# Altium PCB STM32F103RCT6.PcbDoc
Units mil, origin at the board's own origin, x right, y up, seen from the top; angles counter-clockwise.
Board outline 6000 x 4000 mil, 2 copper layers (Top Layer, Bottom Layer); 77 components, 70 nets, 370 pads, 115 vias.
Unrouted connection lines stored in the file: 1.
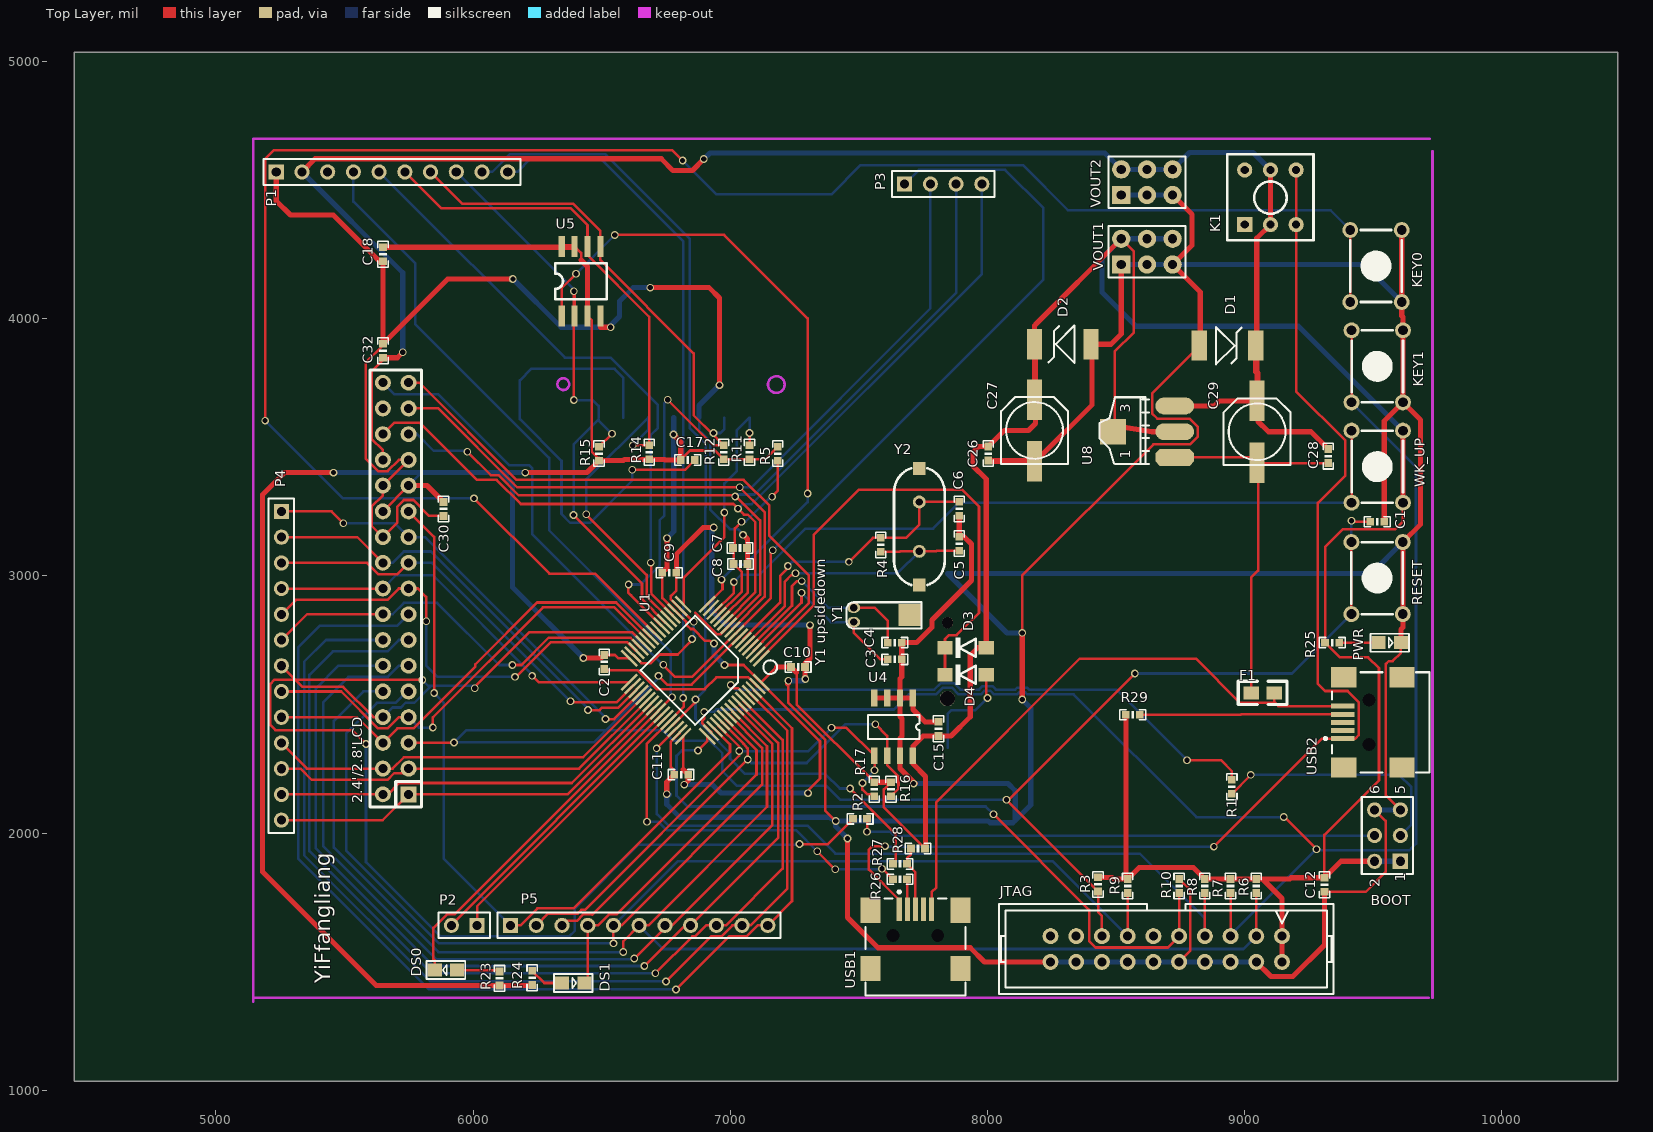
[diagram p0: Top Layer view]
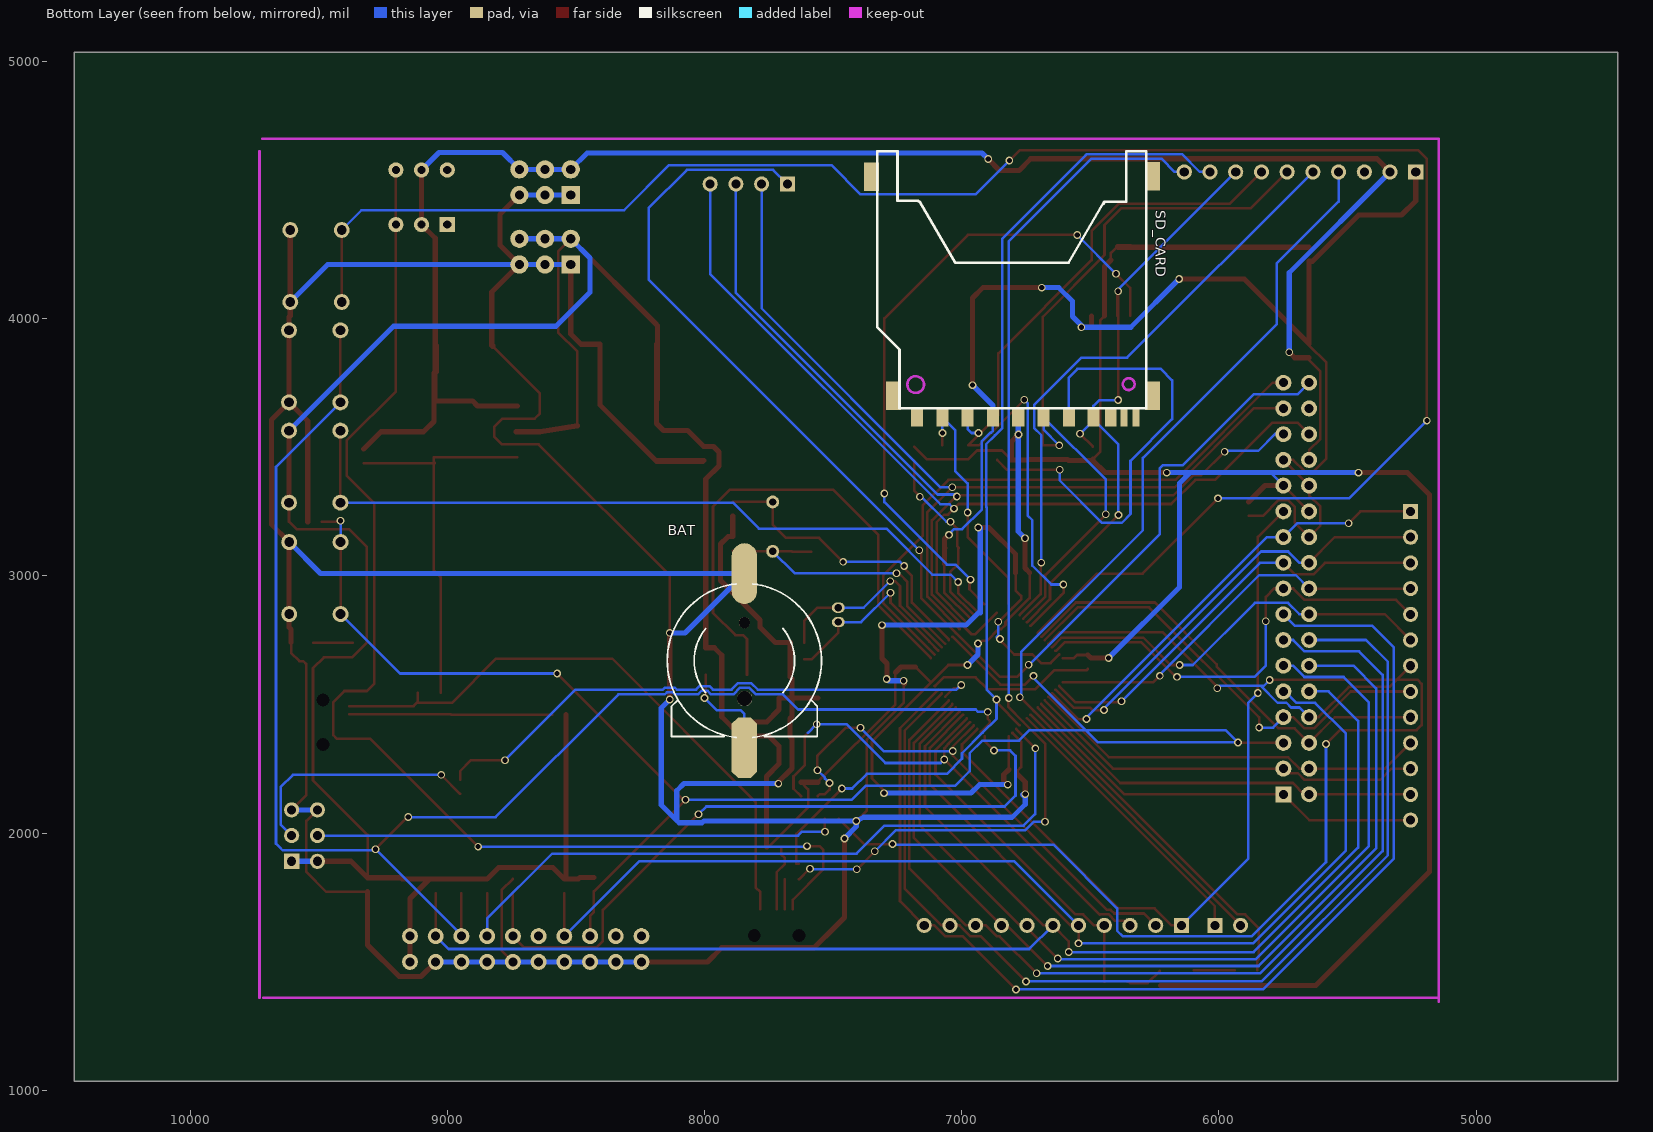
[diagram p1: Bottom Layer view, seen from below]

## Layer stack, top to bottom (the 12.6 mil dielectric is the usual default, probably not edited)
Top Layer: signal copper 1.4
Dielectric: dielectric 12.6, FR-4, Dk 4.8
Bottom Layer: signal copper 1.4

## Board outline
4450,1035 10450,1035 10450,5035 4450,5035

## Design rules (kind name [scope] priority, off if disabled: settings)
Clearance [All] p1: gap=8
PolygonConnect [All] p1: connectstyle=Relief reliefconductorwidth=10 reliefentries=4 polygonreliefangle="90 Angle" airgapwidth=10
RoutingVias [All] p1: holewidth=2 width=50 viastyle="Through Hole" minholewidth=1 minwidth=1 maxholewidth=200 maxwidth=300
SMDNeckDown [All] p1: percent=80.000
SolderMaskExpansion [All] p1: expansion=4
UnConnectedPin [All] p1:
Width Width_3 [InNet('GND')] p1: maxlimit=20 minlimit=10 preferedwidth=20
Width Width_2 [InNet('VCC3.3')] p2: maxlimit=20 minlimit=10 preferedwidth=20
Width Width_1 [InNet('VCC5')] p3: maxlimit=20 minlimit=10 preferedwidth=20
Width [All] p4: maxlimit=10 minlimit=10 preferedwidth=10
28 further rules are at their usual default settings.

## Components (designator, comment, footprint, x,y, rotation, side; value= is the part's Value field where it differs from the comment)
2.4'/2.8'LCD "TFT_LCD" HEAD2*17 5750,2150 r90 top
BAT "BATT" BATM 7845,2670 r180 bottom
BOOT "Header 3X2" HDR2X3#1 9605,1890 r90 top
C1 "104" 0603P 9515,3210 r0 top
C2 "104" 0603P 6510,2665 r270 top
C3 "22" 0603P 7640,2675 r180 top
C4 "22" 0603P 7640,2740 r180 top
C5 "22" 0603P 7890,3125 r270 top
C6 "22" 0603P 7890,3260 r90 top
C7 "10uF" 0603P 7038,3108 r0 top
C8 "104" 0603P 7040,3046 r0 top
C9 "104" 0603P 6763,3012 r0 top
C10 "104" 0603P 7264,2645 r180 top
C11 "104" 0603P 6809,2227 r0 top
C12 "104" 0603P 9310,1799 r270 top
C15 "104" 0603P 7810,2405 r270 top
C17 "104" 0603P 6835,3450 r180 top
C18 "104" 0603P 5650,4250 r270 top
C26 "104" 0603P 8003,3475 r90 top
C27 "220uF" CC6.56.5 8183,3565 r270 top
C28 "104" 0603P 9325,3465 r90 top
C29 "220uF" CC6.56.5 9048,3560 r270 top
C30 "104" 0603P 5885,3260 r270 top
C32 "104" 0603P 5650,3875 r270 top
D1 "SMBJ5.0A" SMBJ 8928,3895 r0 top
D2 "SMBJ3.3A" SMBJ 8298,3900 r180 top
D3 "1N4148" DIODE_SOP 7915,2720 r180 top
D4 "" DIODE_SOP 7915,2615 r180 top
DS0 "LED1" SMDLED 5938,1467 r180 top
DS1 "LED2" SMDLED 6346,1417 r0 top
F1 "500mA" 0805 9025,2545 r0 top
JTAG "JTAG" JTAG_20 8695,1549 r180 top
K1 "BUTTON" BTN8.5*8.5 9000,4365 r90 top
KEY0 "KEY_M" KEY_M 9610,4345 r270 top
KEY1 "KEY_M" KEY_M 9615,3955 r270 top
P1 "VS1053b" HDR1X10 5235,4570 r0 top
P2 "USART" HDR1X2 6016,1641 r180 top
P3 "Header 4" HDR1X4 7678,4523 r0 top
P4 "Header 13" HDR1X13 5255,3250 r270 top
P5 "Header 11" HDR1X11 6146,1641 r0 top
PWR "SYS" SMDLED 9520,2740 r0 top
R1 "Res2" 0603P 8950,2180 r270 top
R2 "Res2" 0603P 7505,2055 r180 top
R3 "Res2" 0603P 8430,1800 r90 top
R4 "1M" 0603P 7585,3120 r90 top
R5 "10R" 0603P 7185,3475 r270 top
R6 "" 0603P 9045,1794 r270 top
R7 "" 0603P 8945,1794 r270 top
R8 "" 0603P 8845,1794 r270 top
R9 "" 0603P 8545,1794 r270 top
R10 "" 0603P 8745,1794 r90 top
R11 "45K" 0603P 7075,3480 r270 top
R12 "45K" 0603P 6975,3480 r270 top
R14 "45K" 0603P 6685,3480 r270 top
R15 "45K" 0603P 6490,3475 r270 top
R16 "" 0603P 7625,2170 r90 top
R17 "" 0603P 7560,2170 r90 top
R23 "1.5K" 0603P 6103,1435 r270 top
R24 "1.5K" 0603P 6230,1437 r270 top
R25 "1.5K" 0603P 9340,2740 r180 top
R26 "22R" 0603P 7660,1820 r0 top
R27 "22R" 0603P 7660,1880 r0 top
R28 "1.5K" 0603P 7730,1940 r180 top
R29 "1.5K" 0603P 8565,2460 r0 top
RESET "KEY_M" KEY_M 9415,2850 r90 top
SD_CARD "sd card" SDCARD_L 7075,3615 r0 bottom
U1 "STM32F103RCT6" LQFP64 7120,2680 r225 top
U4 "24C02" SOP-8 7710,2525 r270 top
U5 "W25Q64" SOIC-8 6345,4010 r90 top
U8 "AMS1117-3.3" AMS1117 8728,3460 r90 top
USB1 "USB" USB/SM0.8-6H5 7720,1395 r270 top
USB2 "USB" USB/SM0.8-6H5 9690,2430 r0 top
VOUT1 "VCC3.3" HDR2X3#2 8520,4210 r0 top
VOUT2 "VCC5" HDR2X3#2 8520,4480 r0 top
WK_UP "KEY_M" KEY_M 9615,3565 r270 top
Y1 "32.768K" XTAL32 7480,2820 r0 top
Y2 "8MHz" XTAL_US 7735,3095 r90 top

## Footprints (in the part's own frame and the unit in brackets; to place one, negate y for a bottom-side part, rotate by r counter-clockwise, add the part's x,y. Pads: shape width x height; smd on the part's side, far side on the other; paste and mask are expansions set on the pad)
0603P [mil]
  rect 30x30 smd: 1(-27,0) 2(27.5,-0.06)
  silkscreen extent -50,-20 50,20
0805 [mil]
  rect 60x50 smd: 1(0,-0.06) 2(90,-0.06)
  silkscreen extent -50,-45 140,45
AMS1117 [mil]
  oct 65x150 smd: 1(0.03,-0.06)
  oval 65x150 smd: 2(100.03,-0.06) 3(200.03,-0.06)
  rect 100x100 smd: 4(100.03,239.94)
  silkscreen extent -26,100 234,293
BATM [mm] "BAT"
  round 1.1 hole 1.1 unplated: 0(0,3.748)
  round 1.5 hole 1.5 unplated: 0(0.025,-3.752)
  oct 2.5x6 smd: 1(0,-8.602)
  oval 2.5x6 smd: 2(0,8.598)
  silkscreen extent -7.62,-7.58 7.62,7.57
BTN8.5*8.5 [mm]
  rect 1.5x1.5 hole 0.8: 1(0,0)
  round 1.5 hole 0.8: 2(0,-2.54) 3(0,-5.08) 4(5.4,-5.08) 5(5.4,-2.54) 6(5.4,0)
  silkscreen extent -1.55,-6.79 6.95,1.71
CC6.56.5 [mm] "SMD;W:6.5mm;L:6.5mm;"
  rect 4x1.5 smd: 1(-3.048,0) 2(3.048,0)
  silkscreen extent -3.3,-3.3 3.3,3.3
DIODE_SOP [mm] "4148"
  rect 1.5x1.3 smd: 1(-2.032,0) 2(2.032,0)
  silkscreen extent -1.02,-1.02 1.02,1.02
HDR1X2 [mm] "Connector; Header; 2 Position"
  rect 1.5x1.5 hole 0.9: 1(0,0)
  round 1.5 hole 0.9: 2(2.54,0)
  silkscreen extent -1.27,-1.27 3.81,1.27
HDR1X4 [mm] "Connector; Header; 4 Position"
  rect 1.5x1.5 hole 0.9: 1(0,0)
  round 1.5 hole 0.9: 2(2.54,0) 3(5.08,0) 4(7.62,0)
  silkscreen extent -1.27,-1.27 8.89,1.27
HDR1X10 [mm] "Connector; Header; 10 Position"
  rect 1.5x1.5 hole 0.9: 1(0,0)
  round 1.5 hole 0.9: 2(2.54,0) 3(5.08,0) 4(7.62,0) 5(10.16,0) 6(12.7,0) 7(15.24,0) 8(17.78,0) 9(20.32,0) 10(22.86,0)
  silkscreen extent -1.27,-1.27 24.13,1.27
HDR1X11 [mm] "Connector; Header; 11 Position"
  rect 1.5x1.5 hole 0.9: 1(0,0)
  round 1.5 hole 0.9: 2(2.54,0) 3(5.08,0) 4(7.62,0) 5(10.16,0) 6(12.7,0) 7(15.24,0) 8(17.78,0) 9(20.32,0) 10(22.86,0) 11(25.4,0)
  silkscreen extent -1.27,-1.27 26.67,1.27
HDR1X13 [mm] "Connector; Header; 13 Position"
  rect 1.5x1.5 hole 0.9: 1(0,0)
  round 1.5 hole 0.9: 2(2.54,0) 3(5.08,0) 4(7.62,0) 5(10.16,0) 6(12.7,0) 7(15.24,0) 8(17.78,0) 9(20.32,0) 10(22.86,0) 11(25.4,0) 12(27.94,0) 13(30.48,0)
  silkscreen extent -1.27,-1.27 31.75,1.27
HDR2X3#1 [mm] "Connector; Header; 3x2 Position"
  rect 1.5x1.5 hole 0.9: 1(0,0)
  round 1.5 hole 0.9: 2(0,2.54) 3(2.54,0) 4(2.54,2.54) 5(5.08,0) 6(5.08,2.54)
  silkscreen extent -1.27,-1.27 6.35,3.81
HDR2X3#2 [mm] "Connector; Header; 3x2 Position"
  rect 1.8x1.8 hole 0.9: 1(0,0)
  round 1.8 hole 0.9: 2(0,2.54) 3(2.54,0) 4(2.54,2.54) 5(5.08,0) 6(5.08,2.54)
  silkscreen extent -1.27,-1.27 6.35,3.81
HEAD2*17 [mil] "PIN:2.54mm;HEAD;"
  rect 62x62 hole 35: 1(0.43,0.42)
  round 62 hole 35: 2(0.43,100.42) 3(100.43,0.42) 4(100.43,100.42) 5(200.43,0.42) 6(200.43,100.42) 7(300.43,0.42) 8(300.43,100.42) 9(400.43,0.42) 10(400.43,100.42) 11(500.43,0.42) 12(500.43,100.42) 13(600.43,0.42) 14(600.43,100.42) 15(700.43,0.42) 16(700.43,100.42) 17(800.43,0.42) 18(800.43,100.42) 19(900.43,0.42) 20(900.43,100.42) 21(1000.43,0.42) 22(1000.43,100.42) 23(1100.43,0.42) 24(1100.43,100.42) 25(1200.43,0.42) 26(1200.43,100.42) 27(1300.43,0.42) 28(1300.43,100.42) 29(1400.43,0.42) 30(1400.43,100.42) 31(1500.43,0.42) 32(1500.43,100.42) 33(1600.43,0.42) 34(1600.43,100.42)
  silkscreen extent -50,-50 1650,150
JTAG_20 [mil] "JTAG,20PIN"
  round 62 hole 35: 1(-450,-50) 2(-450,50) 3(-350,-50) 4(-350,50) 5(-250,-50) 6(-250,50) 7(-150,-50) 8(-150,50) 9(-50,-50) 10(-50,50) 11(50,-50) 12(50,50) 13(150,-50) 14(150,50) 15(250,-50) 16(250,50) 17(350,-50) 18(350,50) 19(450,-50) 20(450,50)
  silkscreen extent -650,-175 650,175
KEY_M [mil] "KEY_MID"
  round 62 hole 38: 1(0.88,0.29) 1(280.85,0.29) 2(0.88,-199.71) 2(280.85,-199.71)
  silkscreen extent 1,-200 281,0
LQFP64 [mm] "LQFP64"
  rect 2.2x0.254 smd: 1(0,0) 2(0,-0.5) 3(0,-1) 4(0,-1.5) 5(0,-2) 6(0,-2.5) 7(0,-3) 8(0,-3.5) 9(0,-4) 10(0,-4.5) 11(0,-5) 12(0,-5.5) 13(0,-6) 14(0,-6.5) 15(0,-7) 16(0,-7.5) 33(10.9,-7.5) 34(10.9,-7) 35(10.9,-6.5) 36(10.9,-6) 37(10.9,-5.5) 38(10.9,-5) 39(10.9,-4.5) 40(10.9,-4) 41(10.9,-3.5) 42(10.9,-3) 43(10.9,-2.5) 44(10.9,-2) 45(10.9,-1.5) 46(10.9,-1) 47(10.9,-0.5) 48(10.9,0)
  rect 0.254x2.2 smd: 17(1.7,-9.2) 18(2.2,-9.2) 19(2.7,-9.2) 20(3.2,-9.2) 21(3.7,-9.2) 22(4.2,-9.2) 23(4.7,-9.2) 24(5.2,-9.2) 25(5.7,-9.2) 26(6.2,-9.2) 27(6.7,-9.2) 28(7.2,-9.2) 29(7.7,-9.2) 30(8.2,-9.2) 31(8.7,-9.2) 32(9.2,-9.2) 49(9.2,1.7) 50(8.7,1.7) 51(8.2,1.7) 52(7.7,1.7) 53(7.2,1.7) 54(6.7,1.7) 55(6.2,1.7) 56(5.7,1.7) 57(5.2,1.7) 58(4.7,1.7) 59(4.2,1.7) 60(3.7,1.7) 61(3.2,1.7) 62(2.7,1.7) 63(2.2,1.7) 64(1.7,1.7)
  silkscreen extent -0.68,-7.56 9.26,1.95
SDCARD_L [mm] "SDCARD_LARGE"
  rect 1.2x1.8 smd: 1(0,0) 2(-2.489,0) 3(-4.983,-0.009) 4(-7.483,-0.009) 5(-9.983,-0.009) 6(-12.483,-0.009) 7(-14.908,-0.009) 9(2.517,-0.009)
  rect 1.1x1.8 smd: 8(-16.612,0)
  rect 0.7x1.8 smd: 10(-17.908,-0.009) 12(-19.101,0)
  rect 1.5x2.8 smd: 11(-20.726,-23.834) 11(-20.726,-2.143) 11(4.826,-2.143) 11(7.01,-23.784)
  Keep-Out Layer circle w0.254: c2.642,-3.26 r0.82
  Keep-Out Layer circle w0.254: c-18.39,-3.3 r0.58
  silkscreen extent -20.13,-26.3 6.44,-0.9
SMBJ [mm]
  rect 1.5x3 smd: 1(-2.667,0) 2(2.921,0)
  silkscreen extent -1.02,-1.85 1.52,1.83
SMDLED [mm]
  rect 1.4x1.27 smd: 1(0.001,-0.002) 2(2.211,-0.002)
  silkscreen extent -0.8,-0.89 3.01,0.89
SOIC-8 [mil] "SOIC"
  rect 80x24 smd: 1(0,0) 2(0,-50.06) 3(0,-100.06) 4(0,-150.06) 5(270,-150) 6(270,-100) 7(270,-50) 8(270,0)
  silkscreen extent 65,-175 205,25
SOP-8 [mil] "SOP"
  rect 65x25 smd: 1(0,0) 2(0,-50) 3(0,-100) 4(0,-150) 5(224.41,-150) 6(224.41,-100) 7(224.41,-50) 8(224.41,0)
  silkscreen extent 65,-175 159,25
USB/SM0.8-6H5 [mm]
  rect 2.3x0.5 smd: 1(-7.85,-1.6) 2(-7.85,-0.8) 3(-7.85,0) 4(-7.85,0.8) 5(-7.85,1.6)
  rect 2.5x2 smd: 6(-7.75,4.45) 7(-1.996,4.45) 8(-7.75,-4.45) 9(-1.996,-4.45)
  round 0.6 hole 1.27 unplated: MH1(-5.25,2.2) MH2(-5.25,-2.2)
  silkscreen extent -9.67,-4.95 0.7,4.95
XTAL32 [mil]
  oval 50x40 hole 28: 1(0,0) 2(0,56)
  rect 92.13x86 smd: ""(220,27)
  silkscreen extent -28,-25 264,77
XTAL_US [mil]
  round 50 hole 28: 1(0,0) 2(192.13,0)
  rect 50x50 smd: ""(-130.32,0) ""(322.44,0)
  silkscreen extent -131,-98 323,98

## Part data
BAT: library part BAT
BOOT: "Header, 3-Pin, Dual row"
C1 C2 C3 C4 C5 C6 C7 C8 C9 C10 C11 C12 C15 C17 C18 C26 C28 C30 C32: library part C
C27 C29: library part CAP
D1 D2: library part SMBJ, "TVS"
D3: library part D
D4: library part D, "1N4148"
DS0 PWR: library part LED2, "Typical RED, GREEN, YELLOW, AMBER GaAs LED"
DS1: "Typical RED, GREEN, YELLOW, AMBER GaAs LED"
F1 R4 R5 R11 R12 R14 R15 R23 R24 R25 R26 R27 R28 R29: library part R
P1: library part "Header 10", "Header, 10-Pin"
P2: library part "Header 2", "Header, 2-Pin"
P3: "Header, 4-Pin"
P4: "Header, 13-Pin"
P5: "Header, 11-Pin"
R1 R2 R3: "Resistor"
R6 R7 R8 R9 R10 R16 R17: library part Res2, "Resistor"
U1: library part STM32F103RDT6
U4: library part 24C256
U5: library part W25X16, "W25X16;SST25VF016;MX25L1605"
U8: library part AMS1117
USB1 USB2: library part USB5
VOUT1 VOUT2: library part "Header 3X2", "Header, 3-Pin, Dual row"
Y1 Y2: library part XTAL, "Crystal Oscillator"

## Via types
v1: diameter 30, hole 20, Top Layer to Bottom Layer, 115 vias

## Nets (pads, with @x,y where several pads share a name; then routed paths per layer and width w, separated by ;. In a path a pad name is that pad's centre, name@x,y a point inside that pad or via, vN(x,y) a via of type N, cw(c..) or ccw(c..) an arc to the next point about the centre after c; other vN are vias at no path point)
BOOT0: R1.1 U1.60 | length 2241.9
  Top Layer w10: v1(7002,2575) 7014.09,2562.91 7031.08,2562.91 U1.60 ; v1(8776,2283) 8907,2283 8950,2240 R1.1
  Bottom Layer w10: v1(7002,2575) 7002,2576 7021,2557 7793.12,2557 7818.94,2582.83 7869.09,2582.83 7894.91,2557 7966.95,2557 7980.95,2571 8019.05,2571 8033.05,2557 8107.95,2557 8115.95,2565 8154.05,2565 8162.05,2557 8502,2557 v1(8776,2283)
BOOT1: 2.4'/2.8'LCD.8 P4.7 R2.2 U1.28 | length 5563.4
  Top Layer w10: P4.7 5337,2568 5495.23,2568 5612.81,2450.43 2.4'/2.8'LCD.8 ; v1(5584,2346) 5530,2400 5232,2400 5212,2420 5212,2580 5227,2595 v1(5803,2595) ; v1@6003.5,2565.5 6218,2780 6619.12,2780 U1.28 ; v1(7269,1957) 7379.44,1957 R2.2
  Bottom Layer w10: v1(5584,2346) 5584,1887 5873,1598 6374,1598 6396,1620 6396,1707 6644,1955 v1@7261,1955 ; 2.4'/2.8'LCD.8 5687.15,2488 5720,2488 5738.43,2506.43 5771.83,2506.43 5837.4,2572 ; v1(5803,2595) 5826,2572 5837.4,2572 ; v1(6007,2563) 5998,2572 5837.4,2572
F_CS: U1.16 U5.1 | length 2580.3
  Top Layer w10: U5.1 6345,4119 v1(6400,4174) ; v1(6551,4325) 6976,4325 7301,4000 v1(7301,3320) ; U1.16 6970,2947.58 6970,2981 v1(6966,2985)
  Bottom Layer w10: v1(6400,4174) v1(6551,4325) ; v1(6966,2985) 7024.45,3043.45 7057.55,3043.45 7301,3286.89 v1(7301,3320)
GND: 2.4'/2.8'LCD.22 2.4'/2.8'LCD.26 2.4'/2.8'LCD.27 BAT.2 BOOT.5 BOOT.6 C1.2 C3.1 C4.1 C5.1 C6.1 C7.2 C8.2 C9.2 C10.1 C11.1 C12.2 C15.1 C18.2 C26.1 C27.2 C30.2 C32.1 D1.1 D2.1 JTAG.4 JTAG.6 JTAG.8 JTAG.10 JTAG.12 JTAG.14 JTAG.16 JTAG.18 JTAG.20 KEY0.1 KEY1.1 P1.1 PWR.2 R10.2 RESET.2 SD_CARD.3 U1.12 U1.18 U1.31 U1.47 U4.1 U4.2 U4.3 U4.4 U4.7 U5.4 VOUT1.1 VOUT1.3 VOUT1.5 VOUT2.1 VOUT2.3 VOUT2.5 | length 26387.2
  Top Layer w10: C32.1 5650,3895.95 5582.58,3828.52 5582.58,3455.2 5631.35,3406.43 5667.8,3406.43 5711.8,3450.43 2.4'/2.8'LCD.27 2.4'/2.8'LCD.26 5649.58,3312.65 5605.58,3268.65 5605.58,3194.43 2.4'/2.8'LCD.22 5705.58,3206.43 5705.58,3268.65 5731.35,3294.43 5767.8,3294.43 5829.73,3232.5 C30.2 ; U1.31 6654.93,2660.68 6691.68,2660.68 6724.92,2693.92 6795.92,2693.92 6842.5,2740.5 ; C11.1 6782,2244 6769.4,2256.6 6769.4,2354.86 6802.64,2388.09 U1.47 ; C9.2 6790.5,2942.36 6769.4,2921.26 6769.4,2908.11 U1.18 v1@6856.51,2821 ; U1.12 7067.5,2933.73 C8.2 ; 7225,2577 7225,2507.11 7369,2363.11 7369,2088 v1(7410,2047) ; v1(8135,2778) 8135,3001 8645,3511 8788,3511 8817,3540 8817,3580 8786,3611 8660,3611 8640,3631 8640,3698 8640,3708 D1.1@8823,3891 ; JTAG.10 8789,1543 8789,1777.56 R10.2 ; C12.2 9470.5,1771.5 9548,1849 9548,2047 BOOT.6 ; BOOT.5 9549,2146 9549,2657 9560,2668 9575.04,2668 9607.04,2700 PWR.2
  Top Layer w20: P1.1 5235,4457 5290,4402 5457,4402 5636.5,4222.5 C18.2 5649.94,3902.06 C32.1 5902,4154 v1(6155,4154) ; U5.4 6495.06,3966 v1(6535,3966) ; v1(6689,4120) 6918,4120 6958,4080 v1(6958,3741.18) ; v1(6753,2151) 6753,2198 C11.1 ; C9.2 6790.5,3083.5 6895,3188 v1@6935.95,3188 ; v1@6856.51,2821 v1(6858,2821) ; v1(7050,3159) 7051,3159 7067.5,3142.5 C7.2@7067.5,3105.94 ; C7.2 C7.2@7067.5,3105.94 ; C8.2 C7.2@7067.5,3105.94 ; v1@7223,2579 7226,2582 v1(7226,2592) ; v1(7292,2599) 7291,2600 C10.1 7291,2659 7310,2678 v1(7310,2808) ; v1(7456,1979) 7456,1672 7491,1637 7574,1554 7933,1554 7988,1499 JTAG.20 ; U4.4 U4.3 U4.2 ; v1@7719,2192 7660,2251 U4.7 7660,2367 7668,2375 7668,2445 7660,2453 U4.2 ; C15.1 7758,2432 7710,2480 U4.1 U4.2 ; C6.1 C5.1 7909,3152 7938,3123 7938,2982 7784,2828 7784,2800 7724,2740 C4.1 C3.1 7667,2607 7660,2600 U4.2 ; C26.1 C26.1@8007,3448 ; v1(8135,2519) v1(8135,2778) ; VOUT1.1 8520,3940 8480,3900 8407,3900 8407,3665 8187,3445 8187,3448 C26.1@8007,3448 ; VOUT2.5 8795,4405 8795,4285 VOUT1.5 8827,4103 8827,3895 8823,3891 D1.1 ; JTAG.4 9102,1442 9187,1442 9309.94,1564.94 C12.2 ; C1.2 9542.5,3601.36 KEY1.1@9615.29,3674.15 ; PWR.2 9607.04,2791 9614.71,2798.67 9614.71,2850.88 9614.71,3130.85 9684,3200.14 9684,3605.44 KEY1.1@9615.29,3674.15 ; KEY0.1@9610.29,4344.12 9610.29,4064.15 9610.29,4011 9615.29,4006 9615.29,3954.12 KEY1.1@9615.29,3674.15 ; C26.1@8007,3448 8183,3448 C27.2 8007,3445 C26.1@8007,3448
  Bottom Layer w10: v1@6858,2761 v1(6858,2821) ; SD_CARD.3 6878.82,3563.38 6886,3556.2 6888.8,3556.2 6923,3522 6923,3259.8 ; 6921.6,3258.4 6999,3181 7030,3181 v1@7050,3161
  Bottom Layer w20: v1(6155,4154) 6343,3966 v1(6535,3966) ; v1@6535,3973.32 6570,4008.32 6570,4067 6623,4120 v1(6689,4120) ; v1(6753,2151) 6753,2139 6753,2112 6804,2061 7381,2061 v1(7410,2047) ; v1@6759,2145 v1@6764,2150 ; v1(6851,2754) v1@6858,2761 ; SD_CARD.3 6878.82,3662 v1(6958,3741.18) ; 6928,2855 v1@6928,3188 ; 6936,2855 6983,2808 v1(7310,2808) ; v1(7050,3159) v1@7050,3161 ; v1(7226,2592) 7285,2592 v1(7292,2599) ; v1(7456,1979) 7410,2025 v1(7410,2047) ; v1@7719,2192 8080,2192 8108,2164 8108,2049 ; 8099,2040 8009.33,2040 8002.33,2047 7885,2047 v1(7410,2047) ; 8105,2046 8168,2109 8168,2486 v1(8135,2519) ; v1(8135,2778) 8075.52,2778 BAT.2 7845,3009 9492.86,3009 RESET.2@9614.71,3130.85 ; JTAG.20 JTAG.18 JTAG.16 JTAG.14 JTAG.12 JTAG.10 JTAG.8 JTAG.6 JTAG.4 ; VOUT1.1 VOUT1.3 VOUT1.5 9464.44,4210 KEY0.1@9610.29,4064.15 ; VOUT2.1 VOUT2.3 VOUT2.5 ; BOOT.6 BOOT.5
  other v1: 7713,2192 6936,3188
IIC_SCL: P5.3 R16.1 U1.53 U4.6 | length 2118.9
  Top Layer w10: P5.3 6363.62,1658.62 6403.47,1658.62 6428.38,1683.53 6463.62,1683.53 6464.07,1683.07 v1@7069.27,2288.27 ; U1.53@6967.89,2430.85 7051,2347.74 7067.74,2329 v1@7067.74,2286.26 ; v1(7564,2423) 7610,2377 U4.6 7610,2264 7654,2220 7654,2172 R16.1
  Bottom Layer w10: v1(7068,2286) 7082,2272 7297,2272 7448,2423 v1(7564,2423) 7598,2389
IIC_SDA: P5.2 R17.1 U1.52 U4.5 | length 2008.9
  Top Layer w10: P5.2 6292,1687 6406.4,1687 6420.93,1701.53 6435.53,1701.53 7035,2301 ; U1.52 6952.97,2417.93 7035,2335.9 v1(7035,2318.45) ; v1(7394,2409) 7451.59,2409 U4.5 7561,2299.59 v1(7561,2244) ; v1(7514,2194) 7514,2169 7532,2151 7552,2151 R17.1
  Bottom Layer w10: v1(7035,2318.45) 7303.45,2318.45 v1(7394,2409) ; v1(7514,2194) 7532,2212 ; 7532,2215 v1(7561,2244)
JTCK: JTAG.9 R10.1 U1.49 | length 2773.7
  Top Layer w10: v1(6875,2321) 6911.21,2357.21 U1.49 ; v1(8023,2073) 8395,1701 8395,1580 8420,1555 8701,1555 JTAG.9 R10.1
  Bottom Layer w10: v1(6875,2321) 6812,2321 6791,2300 6791,2145 6833,2103 7993,2103 v1(8023,2073)
JTDI: JTAG.5 KEY1.2 R7.2 U1.50 | length 5935
  Top Layer w10: v1(6899,2471) 6899,2443.98 6891.89,2436.87 6891.89,2426.1 6925.13,2392.86 U1.50 ; R7.2 8944.94,1682.06 8945,1682 JTAG.5 ; v1(9152,2062) 9154,2062 v1(9279,1937) ; KEY1.2@9415.29,3674.15 KEY1.2@9415.29,3954.12
  Bottom Layer w10: v1(6899,2471) 6936.6,2471 6945.6,2480 7636,2480 7695,2539 7800.57,2539 7826.4,2564.83 7861.63,2564.83 7887.46,2539 7974.4,2539 7988.4,2553 8011.6,2553 8025.6,2539 8115.4,2539 8123.4,2547 8146.6,2547 8154.6,2539 8335,2539 8812,2062 v1(9152,2062) ; JTAG.5 8945,1603 v1(9279,1937) ; v1@9279,1933 9640,1933 9653,1946 9666,1959 9666,3423.44 KEY1.2@9415.29,3674.15
JTDO: 2.4'/2.8'LCD.9 JTAG.13 P5.5 R9.2 U1.55 | length 5545
  Top Layer w10: v1(6546,1571) P5.5 6577,1641 7124,2188 7124,2330.8 U1.55 ; R9.2 8544.94,1682.06 8545,1682 JTAG.13
  Bottom Layer w10: 2.4'/2.8'LCD.9 5742.43,2550.43 5698,2506 5626,2506 5507,2387 5507,1932 5868,1571 v1(6546,1571) ; P5.5 6796,1891 8253,1891 JTAG.13
JTMS: JTAG.7 R8.2 U1.46 | length 2895.5
  Top Layer w10: v1(6714,2329) 6788.72,2403.72 U1.46 ; R8.2 8844.94,1682.06 8845,1682 JTAG.7
  Bottom Layer w10: v1@6715,2329 6715,2074 6760,2029 7300,2029 7409,1920 8592,1920 8845,1667 JTAG.7
JTRST: 2.4'/2.8'LCD.10 JTAG.3 P5.6 R6.2 U1.56 | length 5894.7
  Top Layer w10: v1(6584,1537) 6584,1579 P5.6 6682,1641 7143,2102 7143,2337.26 7008.64,2471.61 U1.56 ; R6.2 9044.94,1682.06 9045,1682 JTAG.3
  Bottom Layer w10: 2.4'/2.8'LCD.10 5573.57,2550.43 5459,2435.85 5459,1943 5865,1537 v1(6584,1537) ; P5.6 6738,1549 8995,1549 JTAG.3
KEY0: KEY0.2 U1.25 | length 7607.3
  Top Layer w10: v1(5192,3603) 5192,4620 5227,4655 6774,4655 v1(6815,4614) ; v1(6004,3301) 6297,3008 6474.64,3008 6555,2927.64 U1.25 ; KEY0.2@9410.29,4064.15 KEY0.2@9410.29,4344.12
  Bottom Layer w10: v1(5192,3603) 5494,3301 v1(6004,3301) ; v1(6815,4614) 6946,4483 7394,4483 7507,4596 8137.66,4596 8312.66,4421 9333.41,4421 KEY0.2@9410.29,4344.12
LCD_BL: 2.4'/2.8'LCD.23 P5.1 U1.51 | length 3020
  Top Layer w10: 2.4'/2.8'LCD.23 5849,3151 v1(5849,2544) ; P5.1 6184,1641 6250,1707 6391,1707 6999,2315 6999,2344.44 U1.51
  Bottom Layer w10: v1(5849,2544) 5886,2507 5886,1901 P5.1
LCD_CS: 2.4'/2.8'LCD.1 P4.13 U1.40 | length 1631.6
  Top Layer w10: P4.13 5649.15,2050 2.4'/2.8'LCD.1 6367.72,2150.43 U1.40
LCD_D0: 2.4'/2.8'LCD.6 P4.9 U1.26 | length 1763.3
  Top Layer w10: P4.9 5550,2450 2.4'/2.8'LCD.6 5705.58,2406.43 5767.8,2406.43 6009,2647.62 6009,2656 6249,2896 6556.42,2896 6688.9,2763.52 U1.26
LCD_D1: 2.4'/2.8'LCD.7 P4.8 U1.27 | length 1787.7
  Top Layer w10: P4.8 5487.78,2550 5631.35,2406.43 5667.8,2406.43 5711.8,2450.43 2.4'/2.8'LCD.7 ; v1(5844,2410) 5844,2449 5845,2450 6272.5,2877.5 6272,2878 6548.96,2878 U1.27
  Bottom Layer w10: 2.4'/2.8'LCD.7 5790,2410 v1(5844,2410)
LCD_D5: 2.4'/2.8'LCD.11 P5.7 U1.57 | length 3616.8
  Top Layer w10: v1(6627,1512) 6746,1631 P5.7 6774,1641 7164,2031 7164,2346.48 U1.57
  Bottom Layer w10: 2.4'/2.8'LCD.11 5711.8,2650.43 5667.8,2606.43 5515.43,2606.43 5417,2508 5417,1950 5858,1509 6624,1509 v1(6627,1512)
LCD_D6: 2.4'/2.8'LCD.12 P5.8 U1.58 | length 3694.8
  Top Layer w10: v1(6666,1483) 6824,1641 P5.8 7186,1981 7186,2349.93 7036.48,2499.45 U1.58
  Bottom Layer w10: 2.4'/2.8'LCD.12 5477,2650.43 5389,2562.43 5389,1940 5846,1483 v1(6666,1483)
LCD_D7: 2.4'/2.8'LCD.13 P5.9 U1.59 | length 4049.4
  Top Layer w10: v1(6709,1455) 6852.47,1598.47 6863.62,1598.47 6906.14,1641 P5.9 6983,1641 7204,1862 7204,2362.16 U1.59
  Bottom Layer w10: 2.4'/2.8'LCD.13 5711.8,2750.43 5667.8,2706.43 5455.43,2706.43 5364,2615 5364,1930 5839,1455 v1(6709,1455)
LCD_D8: 2.4'/2.8'LCD.14 P5.10 U1.61 | length 4143.2
  Top Layer w10: v1(6750,1423) 6925.47,1598.47 6965.93,1598.47 7008.46,1641 P5.10 7079,1641 7222,1784 7222,2397.45 7078.24,2541.21 U1.61
  Bottom Layer w10: 2.4'/2.8'LCD.14 5428.43,2750.43 5344,2666 5344,1913 5834,1423 v1(6750,1423)
LCD_D9: 2.4'/2.8'LCD.15 P5.11 U1.62 | length 4459.5
  Top Layer w10: v1(6789,1392) 6995.47,1598.47 7063.62,1598.47 7106.14,1641 P5.11 7240,1735 7240,2407.29 7092.16,2555.13 U1.62
  Bottom Layer w10: 2.4'/2.8'LCD.15 5705.58,2806.43 5406,2806.43 5320,2720.43 5320,1901 5829,1392 v1(6789,1392)
LCD_D10: 2.4'/2.8'LCD.16 P4.6 U1.29 | length 1613.7
  Top Layer w10: P4.6 5355.43,2850.43 2.4'/2.8'LCD.16 ; v1(6153,2653) 6188,2653 6294.08,2759.08 6612.2,2759.08 U1.29
  Bottom Layer w10: 2.4'/2.8'LCD.16 5687.35,2850.43 5731.35,2894.43 5860.57,2894.43 6102,2653 v1(6153,2653)
LCD_D11: 2.4'/2.8'LCD.17 P4.5 U1.30 | length 1790.2
  Top Layer w10: P4.5 5311.43,2906.43 5667.8,2906.43 5711.8,2950.43 2.4'/2.8'LCD.17 5785.57,2950.43 5818,2918 v1(5818,2823) ; v1(6163,2607) 6167.46,2607 6301.53,2741.08 6599.98,2741.08 6633.22,2707.84 U1.30
  Bottom Layer w10: v1(5818,2823) 5818,2651 5862,2607 v1(6163,2607)
LCD_D12: 2.4'/2.8'LCD.18 P4.4 U1.33 | length 1540.1
  Top Layer w10: P4.4 5649.15,2950 2.4'/2.8'LCD.18 ; v1@6237,2605 6256.65,2585.35 U1.33
  Bottom Layer w10: 2.4'/2.8'LCD.18 5701.15,3002 5843.6,3002 6230,2615.6 v1(6230,2611)
LCD_D13: 2.4'/2.8'LCD.19 P4.3 U1.34 | length 1653.1
  Top Layer w10: P4.3 5587.78,3050 5631.35,3006.43 5705.58,3006.43 2.4'/2.8'LCD.19 ; v1(6379,2512) 6382,2509 6559.26,2509 U1.34
  Bottom Layer w10: 2.4'/2.8'LCD.19 5840.57,3050.43 v1(6379,2512)
LCD_D14: 2.4'/2.8'LCD.20 P4.2 U1.35 | length 1726
  Top Layer w10: P4.2 5550,3150 2.4'/2.8'LCD.20 ; v1(6447,2478) 6492,2478 6501,2487 6565.09,2487 U1.35
  Bottom Layer w10: 2.4'/2.8'LCD.20 5687.35,3050.43 5731.35,3094.43 5836.17,3094.43 v1@6447,2483.6
LCD_D15: 2.4'/2.8'LCD.21 P4.1 U1.36 | length 1767.7
  Top Layer w10: P4.1 5450,3250 v1(5496,3204) ; v1(6515,2443) 6548.93,2443 U1.36
  Bottom Layer w10: v1(5496,3204) 5696,3204 2.4'/2.8'LCD.21 5814.17,3150.43 v1@6515,2449.6
LCD_RD: 2.4'/2.8'LCD.4 P4.10 U1.37 | length 1565.4
  Top Layer w10: P4.10 5354.57,2250.43 2.4'/2.8'LCD.4 5687.35,2250.43 5731.35,2294.43 6428.2,2294.43 U1.37
LCD_RS: 2.4'/2.8'LCD.2 P4.12 U1.39 | length 1582
  Top Layer w10: P4.12 5649.15,2150 2.4'/2.8'LCD.2 5669.19,2150.43 5713.19,2194.43 6383.88,2194.43 U1.39
LCD_WR: 2.4'/2.8'LCD.3 P4.11 U1.38 | length 1568.5
  Top Layer w10: P4.11 5329.54,2250 5373.12,2206.43 5667.8,2206.43 5693.8,2232.43 5731.58,2232.43 2.4'/2.8'LCD.3 6412.04,2250.43 U1.38
LED0: DS0.2 P1.4 U1.41 | length 4013.8
  Top Layer w10: DS0.2 5850.96,1505 5845.96,1510 5845.96,1631.1 5898.38,1683.53 5928.66,1683.53 U1.41 6719.99,2473.99 v1(6774,2528)
  Bottom Layer w10: P1.4 5535,4455 5775,4215 5775,3979 6296,3458 6296,3177 6769,2704 v1@6769,2533
LED1: DS1.2 P5.4 U1.54 | length 1388.5
  Top Layer w10: DS1.2@6445.04,1420.94 6446,1421.9 P5.4 6485.86,1641 6528.38,1683.53 6558.53,1683.53 7102,2227 7102,2322.58 7056.78,2367.8 6980.81,2443.77 U1.54
MP3_DREQ: P1.9 R27.1 U1.45 | length 4112.7
  Top Layer w10: U1.45 v1@6861.48,2505 ; v1@6858,2519 v1(6865,2519) ; v1(7466,2173) 7643,1996 7643,1880 R27.1
  Bottom Layer w10: P1.9 6074.86,4570 6144.34,4639.48 6513.52,4639.48 6517,4636 6842.2,4310.8 6842.2,3574.54 6871,3545.74 6904.74,3512 6904.74,3267 6903.6,3265.86 6903.6,2557.6 v1(6865,2519) 6865,2444 6919,2390 6999,2310 6999,2289 7058,2230 7369,2230 7426,2173 v1(7466,2173)
MP3_RST: P1.10 R26.1 U1.44 | length 4200.4
  Top Layer w10: v1(6676,2044) 6676,2347.35 U1.44 6820,2491.35 6820,2515 6820,2522 v1(6817,2525) ; v1(7338,1929) v1(7408,1859) ; v1(7590,1861) 7592,1861 R26.1
  Bottom Layer w10: P1.10 6172.61,4570 6224.09,4621.48 6496.52,4621.48 6817.01,4300.99 v1@6817.01,2530.01 ; v1(6676,2044) 6719.54,2044 6752.54,2011 7256,2011 v1(7338,1929) ; v1(7408,1859) 7588,1859 v1(7590,1861)
MP3_SCK: P1.6 R14.1 SD_CARD.5 U1.21 U5.6 | length 2964.2
  Top Layer w10: P1.6 5876,4429 6379,4429 6445,4363 U5.6 6445,4247 6685,4007 R14.1 v1(6621,3507) ; v1(6440,3239) 6440,3238.46 6675,3003.46 6675,2918.99 U1.21
  Bottom Layer w10: v1(6440,3239) 6440,3373.39 SD_CARD.5 6681.97,3567.97 v1(6621,3507)
MP3_SI: P1.7 R12.1 SD_CARD.2 U1.23 U5.5 | length 3204.1
  Top Layer w10: P1.7 5958,4447 6389,4447 6495,4341 U5.5 6495,4227 6858,3864 6858,3624 v1@6935,3547 ; v1(6605,2966) 6603,2964 6603,2935.31 6614.66,2923.66 U1.23 ; v1(6757,3684) 6934,3507 R12.1 v1@6935,3547 ; v1(6935,3555) v1@6935,3547
  Bottom Layer w10: v1(6605,2966) 6652,2966 6726,3040 6726,3216 6743,3233 6743,3670 v1(6757,3684) ; v1(6935,3555) 6962,3555 6977,3570 SD_CARD.2
MP3_SO: P1.8 R15.1 SD_CARD.7 U1.22 U5.2 | length 2441.7
  Top Layer w10: v1(6391,3236) 6657,2970 6657,2909.15 U1.22 ; v1(6392,3683) v1(6392,4106) ; U5.2 v1@6395.06,4102.94 ; R15.1 v1(6540,3552)
  Bottom Layer w8: SD_CARD.7@6488.07,3606.6 SD_CARD.7
  Bottom Layer w10: P1.8 v1@6391,4114 ; v1(6391,3236) 6391,3509.53 6488.07,3606.6 6488.07,3603.93 v1(6540,3552) ; v1(6392,3683) 6465.07,3683 6488.07,3660 SD_CARD.7
MP3_XDCS: P1.5 U1.20 | length 2330.3
  Top Layer w10: v1(6691,3051) 6685,3051 6693,3043 6693,2928.83 U1.20
  Bottom Layer w10: P1.5 6357,3848 6534.39,3848 6718.59,3663.8 6718.59,3574.54 6691,3546.95 v1(6691,3051)
NetBAT_1: BAT.1 D4.1 | length 402.3
  Top Layer w10: v1@7995,2525 D4.1
  Bottom Layer w10: BAT.1 7845,2463 7860,2478 7953,2478 v1(8000,2525)
NetBOOT_3: BOOT.3 R1.2 | length 954.2
  Top Layer w10: R1.2 v1(9023.44,2226)
  Bottom Layer w10: v1(9023.44,2226) 9600,2226 9648,2178 9648,2033 BOOT.3
NetBOOT_4: BOOT.4 R2.1 | length 2029.2
  Top Layer w10: v1(7532,2005) R2.1
  Bottom Layer w10: v1(7532,2005) 7621,2005 7636,1990 BOOT.4
NetC2_2: C2.2 U1.63 | length 661.3
  Top Layer w10: C2.2 6514.59,2632.84 6639.9,2632.84 6713.75,2559 6900.33,2559 6946,2604.67 7025.67,2604.67 7070.46,2604.67 7103.7,2571.43 U1.63
NetC3_2: C3.2 U1.3 Y1.1 | length 768.9
  Top Layer w10: U1.3 7092.16,2710.22 7125.4,2743.46 7125.4,2743.94 7277,2895.54 v1(7277,2934) ; Y1.1 7480,2780 7584.94,2675.06 C3.2
  Bottom Layer w10: v1(7277,2934) 7391,2820 Y1.1
NetC4_2: C4.2 U1.4 Y1.2 | length 833.5
  Top Layer w10: U1.4 7078.24,2722.24 7240,2884 7240,2960 7259,2979 v1(7278,2979) ; Y1.2 7560,2876 7612.5,2823.5 C4.2
  Bottom Layer w10: v1(7278,2979) 7381,2876 Y1.2
NetC5_2: C5.2 R4.1 U1.5 Y2.1 | length 1182.9
  Top Layer w10: U1.5 7212,2883.36 7212,2977 7237,3002 v1@7259,3002 ; R4.1 7659,3093 7661,3095 Y2.1 7800.53,3095 7803.03,3097.5 C5.2
  Bottom Layer w10: v1(7254,3010) 7650,3010 Y2.1
NetC6_2: C6.2 R4.2 U1.6 Y2.2 | length 1189.6
  Top Layer w10: U1.6 7050.4,2751.98 7194,2895.58 7194,3000 7221,3027 7229,3027 7224,3032 v1(7224,3038) ; v1(7461,3054) 7554.5,3147.5 R4.2 7682.5,3147.5 7735,3200 Y2.2 7812,3287.13 7812.37,3287.5 C6.2
  Bottom Layer w10: v1(7224,3038) 7240,3054 v1(7461,3054)
NetC7_1: C7.1 C8.1 R5.2 U1.13 | length 726.5
  Top Layer w10: U1.13 7045,2939.06 7045,3014 C8.1 C7.1@7013,3106 ; C7.1 7018,3115 7018,3184 v1(7044,3210) ; v1@7165.5,3312.5 7184.94,3331.94 R5.2
  Bottom Layer w10: v1(7044,3210) 7060,3210 v1@7160,3310
  other v1: 7163,3307
NetC17_1: C17.1 SD_CARD.6 | length 1833
  Top Layer w10: v1(6619,3412) 6824,3412 C17.1
  Bottom Layer w10: SD_CARD.6 6583.54,3770.46 6550,3804 6226,3804 6182,3760 6182,3609 6344,3447 6344,3240 6378,3206 6454,3206 6619,3371 v1(6619,3412)
NetC28_1: C28.1 C29.2 F1.1 U8.1 | length 1529.2
  Top Layer w10: U8.1 8732.06,3460.03 9052,3460.03 C29.2@9052,3438 ; F1.1 9025,2993 9052,3020 C29.2@9052,3438 ; C29.2 9048,3438 C29.2@9052,3438 ; C28.1 C29.2@9052,3438
NetD3_2: D3.2 D4.2 U1.1 | length 2033
  Top Layer w10: U1.1 7324,2884 7324,3159 7500,3335 7901,3335 7967,3269 7967,2856 7880,2769 7850,2769 7835,2754 D3.2 D4.2
NetDS0_1: DS0.1 R23.1 | length 160
  Top Layer w10: DS0.1 6053.97,1467.06 R23.1@6097.94,1467.06
NetDS1_1: DS1.1 R24.1 | length 153.5
  Top Layer w8: DS1.1@6346,1415 6346,1420.94 DS1.1@6358.03,1420.94
  Top Layer w10: R24.1 6277.06,1416.94 DS1.1
NetF1_2: F1.2 USB1.5 USB2.5 | length 2351.5
  Top Layer w10: USB1.5 7782.99,1770.99 7801,1789 7801,2120.32 8358.68,2678 8810,2678 8982,2506 9115,2506 9115,2509 ; F1.2 9115,2509 ; USB2.5 9131.01,2492.99 9115,2509
NetK1_3: K1.3 K1.4 USB1.1 USB2.1 | length 4807.4
  Top Layer w10: v1(7602,1949) 7553,1949 7539,1935 7539,1858 7657.01,1739.99 USB1.1 ; v1(8879.98,1947) 9299.99,2367.01 USB2.1 9430.01,2367.01 9443,2380 9443,2509 9400,2552 9312,2552 9284,2580 9284,3283 9391,3390 9391,3526.18 9200,3717.18 K1.3 K1.4
  Bottom Layer w10: v1@7602,1947 v1(8879.98,1947)
NetPWR_1: PWR.1 R25.1 | length 153.1
  Top Layer w10: R25.1 9443,2740 9443.06,2739.94 PWR.1
NetR26_2: R26.2 USB1.2 | length 116.3
  Top Layer w10: R26.2 7687.5,1762 7688.5,1761 USB1.2
NetR27_2: R27.2 R28.2 USB1.3 | length 255.7
  Top Layer w10: R28.2 7702.5,1917 7687.5,1902 R27.2 7720,1847.44 USB1.3
NetR29_2: R29.2 USB2.4 | length 789.1
  Top Layer w10: R29.2 8985,2459.94 8986.56,2461.49 USB2.4
PC0: 2.4'/2.8'LCD.34 P3.1 U1.8 | length 4830.5
  Top Layer w10: v1(6740,2654) 6740,2652 6785,2607 6852.13,2607 U1.8 7158,2912.87 7158,3097 v1@7160,3099
  Bottom Layer w10: 2.4'/2.8'LCD.34 5695,3705 5865,3705 6141,3429 6219,3429 6231,3417 6231,3161 v1@6735.5,2656.5 ; v1(7165,3099) 8217,4151 8217,4429 8068,4578 7733,4578 P3.1
PC1: 2.4'/2.8'LCD.31 P3.2 U1.9 | length 3571.4
  Top Layer w10: 2.4'/2.8'LCD.31 5865.57,3650.43 6172,3344 v1(7037,3344) 7134,3247 7134,2919.09 7008.64,2793.74 U1.9
  Bottom Layer w10: v1(7037,3344) 7082,3344 7778,4040 P3.2
PC2: 2.4'/2.8'LCD.29 P3.3 U1.10 | length 3809.5
  Top Layer w10: v1(5978,3482) 6069,3391 6099.54,3391 6177.54,3313 v1@7011,3313 ; U1.10 6961.49,2772.04 6961.04,2772.04 ; v1@7021.23,3310.23 7116,3215.46 7116,2927 6961.04,2772.04 ; 6877.97,2842.4 6948.33,2772.04 6961.04,2772.04 ; 6877.97,2842.4 6864.35,2856.02 6877.97,2842.4
  Bottom Layer w10: 2.4'/2.8'LCD.29@5750,3551 5782,3551 5847,3486 5974,3486 v1(5978,3482) ; v1(7019,3308) 7027,3316 7094,3316 7878,4100 P3.3
PC3: 2.4'/2.8'LCD.30 P3.4 U1.11 | length 3739.8
  Top Layer w10: 2.4'/2.8'LCD.30 5693.58,3594.43 5793.58,3594.43 6015,3373 6092.09,3373 6186.09,3279 7012,3279 v1(7030,3261) 7053,3238 7068,3238 7098,3208 7098,2936.39 U1.11
  Bottom Layer w10: v1(7030,3261) 7047,3278 7083,3278 7978,4173 P3.4
RESET: 2.4'/2.8'LCD.5 C1.1 JTAG.15 R3.1 RESET.1 U1.7 | length 6566.6
  Top Layer w10: 2.4'/2.8'LCD.5 v1@5924.43,2350.43 ; v1(6721,2611) 6755,2577 6849.97,2577 U1.7 ; v1(8074,2129) 8082,2129 v1(8573,2620) ; v1@8078,2125 R3.1 8430,1693 8445,1678 JTAG.15 ; RESET.1@9414.71,2850.88 RESET.1@9414.71,3130.85 ; v1(9415,3214) 9419,3210 C1.1
  Bottom Layer w8: v1@6719,2601 6721,2601 v1(6721,2611)
  Bottom Layer w10: v1@6719,2601 6470,2352 v1(5926,2352) 5974,2400 6736,2400 6777,2359 6920,2359 6969,2310 6969,2240 7025,2184 7373,2184 7428,2129 v1(8074,2129) ; v1(8573,2620) 9183.83,2620 RESET.1@9414.71,2850.88 ; RESET.1@9414.71,3130.85 9414.71,3213.71 v1(9415,3214)
RXD: P2.1 U1.43 | length 1107.9
  Top Layer w10: P2.1 6016,1715.19 U1.43
SD_CS: R11.1 SD_CARD.1 U1.17 | length 941.3
  Top Layer w10: U1.17 6818.5,2890.73 6818.5,2991.5 6977,3150 v1(6977,3246) ; R11.1 v1(7075,3555)
  Bottom Layer w10: v1(6977,3246) 6977,3359 7026,3408 7026,3566 SD_CARD.1 v1(7075,3555)
T_CS: 2.4'/2.8'LCD.33 U1.2 | length 2325.9
  Top Layer w10: 2.4'/2.8'LCD.33 5791.57,3750.43 6169,3373 7052,3373 7152,3273 7152,3155.37 7306,3001.37 7306,2893.84 U1.2
TXD: P2.2 U1.42 | length 1157.5
  Top Layer w10: P2.2 5916,1643.03 U1.42
VCC3.3: 2.4'/2.8'LCD.24 2.4'/2.8'LCD.25 BOOT.1 BOOT.2 C2.1 C9.1 C10.2 C11.2 C12.1 C15.2 C17.2 C18.1 C26.2 C27.1 C30.1 D2.2 D3.1 JTAG.1 JTAG.2 R3.2 R5.1 R6.1 R7.1 R8.1 R9.1 R11.2 R12.2 R14.2 R15.2 R16.2 R17.2 R23.2 R24.2 R25.2 R28.1 R29.1 SD_CARD.4 U1.19 U1.32 U1.48 U1.64 U4.8 U5.3 U5.7 U5.8 U8.2 U8.4 VOUT1.2 VOUT1.4 VOUT1.6 WK_UP.1 | length 22468.3
  Top Layer w10: 2.4'/2.8'LCD.24 2.4'/2.8'LCD.25 ; U5.7 6420,4255 6420,4227 ; U5.3 6462,3993.06 6462,3481.62 R15.2@6489.94,3453.68 ; C2.1 6552,2692 6564,2680 U1.32 ; C9.1 6736,2913.67 6830,2819.67 6830,2809.4 6846.4,2793 6856.67,2793 6902.67,2747 6921,2747 v1@6931,2737 ; C17.2 6844.44,3487 6940.44,3487 R12.2 R11.2 7135.5,3452.5 R5.1 ; 6816.56,2246.88 U1.48 ; v1(6978,2653) 7052.35,2653 U1.64 ; 7179.72,2645.06 U1.64 ; 7258,2623.56 7258,2499.56 R17.2 ; v1@7302,2165 7349,2212 7349,2356.35 U1.64 ; 7597,2120 7597,2169.44 ; R16.2 7597,2169.44 ; R28.1 7597,2100 7597,2169.44 ; U8.4@8494.06,3583.03 8494.06,3873 ; 8494.06,3871.47 8569,3946.4 8569,4261 VOUT1.2 ; C12.1 9310,1993 9522,2205 9522,2641 9480,2683 9369.56,2683 R25.2 9312.5,3111.59 9381.91,3181 9586,3181 9615.29,3210.29 WK_UP.1@9615.29,3284.15
  Top Layer w20: v1(5458,3401) 5268,3401 5182,3315 5182,1849 5623.5,1407.5 5994.37,1407.5 R23.2 R24.2@6227.94,1407.5 ; C18.1 6392,4277 U5.7 U5.8 ; 2.4'/2.8'LCD.25 5821.57,3350.43 C30.1 ; v1(6203,3401) 6443.44,3401 R15.2 ; 6420,4227 6445.06,4201.94 U5.3 ; v1(6429,2680) 6498,2680 C2.1 ; R15.2@6489.94,3453.68 R15.2 ; C9.1 6754,3030 v1(6754,3146) ; v1(6779,3549) 6807.5,3520.5 C17.2 6747.44,3450.06 6745,3452.5 R14.2 6589,3452.5 6584,3447.5 R15.2 ; 6816.56,2246.88 C11.2 6836.5,2203.5 v1(6821,2188) ; v1@6931,2737 v1(6937,2737) ; 7179.72,2645.06 C10.2 7258,2623.56 ; R17.2 R16.2 ; R28.1@7759,1945 7759,2220 7710,2269 U4.8 7710,2337 7750.5,2377.5 C15.2 7858.5,2377.5 7933,2452 7933,2691 7962,2720 D3.1 7995,3376 7944,3427 7944,3481 7965.5,3502.5 C26.2 8065.56,3565 8069.56,3565 8160,3565 8187,3592 D2.2@8187,3900 ; C27.1 D2.2 8183,3973 ; 8187,3977 VOUT1.2 ; R3.2 8484,1827.5 8490.5,1821 R9.1 ; U8.4@8494.06,3583.03 8640,3560.03 U8.2 U8.2@8732.06,3560.03 ; R29.1 8538,1828 R9.1 ; JTAG.2 JTAG.1 9145,1745 9069,1821 R6.1 ; BOOT.2 9374,1890 C12.1 9180,1826 9175,1821 R6.1 ; WK_UP.1@9615.29,3284.15 WK_UP.1@9615.29,3564.12 ; R9.1 8590,1866 8800,1866 R8.1 R7.1 R6.1
  Bottom Layer w10: 2.4'/2.8'LCD.25 5800.15,3401
  Bottom Layer w20: v1(5458,3401) 5800.15,3401 ; v1(6203,3401) 5800.15,3401 ; v1(6429,2680) 6154,2955 6154,3360 6113,3401 5800.15,3401 ; v1(6754,3146) 6780.39,3172.39 v1@6780.39,3550.39 ; v1(6779,3549) v1@6780.39,3550.39 ; SD_CARD.4 v1@6780.39,3550.39 ; v1(6821,2188) 6931,2188 6964,2155 v1(7302,2155) ; v1@6931,2737 v1(6937,2737) 6937,2694 v1(6978,2653) ; VOUT1.6 VOUT1.4 VOUT1.2 8445,4235 8445,4102 8577,3970 9209.41,3970 WK_UP.1@9615.29,3564.12 ; BOOT.2 BOOT.1
VCC5: 2.4'/2.8'LCD.28 C28.2 C29.1 C32.2 D1.2 K1.2 K1.5 P1.2 U8.3 VOUT2.2 VOUT2.4 VOUT2.6 | length 7157.1
  Top Layer w10: 2.4'/2.8'LCD.28 5649.58,3488.2 5605.58,3532.2 5605.58,3794.43 C32.2@5649.94,3838.79
  Top Layer w20: P1.2 5386,4621 6731.82,4621 6776.82,4576 6853,4576 v1(6897,4620) ; C32.2 5705.5,3847.5 v1(5727,3869) ; U8.3 8732.06,3660.03 8882,3660.03 8901.97,3680 C29.1 ; D1.2 9043,3793 9048,3788 C29.1 ; K1.5 K1.2 9047,4312 9047,3793 9052,3788 C29.1@9052,3680 ; C28.2 9257.56,3560 9092,3560 9052,3600 C29.1@9052,3680 ; C29.1 C29.1@9052,3680
  Bottom Layer w20: P1.2 5727,4178 v1(5727,3869) ; v1(6897,4620) 6921,4644 8456,4644 VOUT2.2 VOUT2.4 VOUT2.6 8785,4645 9032.6,4645 K1.5
WK_UP: U1.14 WK_UP.2 | length 2956.4
  Top Layer w10: U1.14 6941.43,2860.95 7014,2933.52 v1(7014,2976) ; WK_UP.2@9415.29,3284.15 WK_UP.2@9415.29,3564.12
  Bottom Layer w10: v1(7014,2976) 7042,3004 7114,3004 7293,3183 7789,3183 7890.15,3284.15 WK_UP.2@9415.29,3284.15
pads on no net: 2.4'/2.8'LCD.32 BAT.0 JTAG.11 JTAG.17 JTAG.19 K1.1 K1.6 P1.3 SD_CARD.8 SD_CARD.9 SD_CARD.10 SD_CARD.11 SD_CARD.12 U1.15 U1.24 USB1.4 USB1.6 USB1.7 USB1.8 USB1.9 USB1.MH1 USB1.MH2 USB2.2 USB2.3 USB2.6 USB2.7 USB2.8 USB2.9 USB2.MH1 USB2.MH2 Y1. Y2.

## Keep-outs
Keep-Out Layer:
  lines w10: 5145,1345 5145,4699 9720,4699 ; 5145,1360 9715,1360 ; 9730,1360 9730,4650

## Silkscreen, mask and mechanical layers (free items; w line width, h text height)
Top Overlay:
  text "Y1 upsidedown" at 7370,2650 h40 r90
  text "YiFfangliang" at 5445,1415 h60 r90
